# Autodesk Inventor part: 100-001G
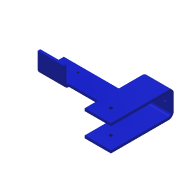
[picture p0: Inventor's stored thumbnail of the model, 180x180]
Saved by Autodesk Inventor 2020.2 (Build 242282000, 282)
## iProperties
Created: 2014-01
Part Number: 100-001G
Material: Ogólny
Document SubType Name: Modeling
Designer: F.Stasiak
Density: 1 g/cm^3
Appearance: Niebieska - farba ścienna - lśniąca
Manager: www.cadconsulting.pl
Company: Fabian Stasiak CAD Consulting
Author: F.Stasiak
Subject: Zbiór ćwiczeń. Autodesk Inventor 2020. Kurs podstawowy
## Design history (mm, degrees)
sketch "Szkic2"
  geometry: L1 (20, 120)-(20, 5); L2 (20, 5)-(-20, 5); L3 (-20, 5)-(-20, 120); L4 (-25, 120)-(-25, 0); L5 (-25, 0)-(25, 0); L6 (25, 0)-(25, 120); L7 (25, 120)-(20, 120); L8 (-20, 120)-(-25, 120); 2 further points
  constraints: 16 end point, 3 equal length, 3 perpendicular, 1 coincident, 1 midpoint, 1 parallel, 1 vertical, 2 other
  dimensions: "d2" = 5 distance of L6.end L1.start; "d3" = 120 distance of L5.end L6.end; "d4" = 50 distance between parallel lines of L6 L4
extrude "Wyciągnięcie proste1" new body sketch "Szkic2" stored distance "d5" = 50; taper "d6" = 0 deg
fillet "Zaokrąglenie1" dims "d7" = 5
fillet "Zaokrąglenie2" dims "d8" = 10
sketch "Szkic3"
  geometry: L1 (50, 0)-(50, -30) reference; L2 (12.5, -15)-(37.5, -15); 4 further points
  constraints: 3 coincident, 2 end point, 1 midpoint, 1 perpendicular
  dimensions: "d9" = 25 distance of L2.start L2.end
hole "Otwór1" sketch "Szkic3" at (12.5, -15), (37.5, -15) diameter "d10" = 6.5; stored, may be unused: countersink angle "d14" = 90 deg, drill point angle "d16" = 118 deg; dims "d11" = 6, "d12" = 4, "d13" = 2, "d15" = 8
sketch "Szkic4"
  geometry: L1 (0, 0)-(50, 0) reference; 3 further points
  constraints: 1 midpoint, 1 vertical alignment
  dimensions: "d17" = 25 distance from line of L1 point (25, 25)
hole "Otwór2" sketch "Szkic4" at (25, 25) diameter "d18" = 6.5; stored, may be unused: countersink angle "d22" = 90 deg, drill point angle "d24" = 118 deg; dims "d19" = 6, "d20" = 4, "d21" = 2, "d23" = 8
sketch "Szkic5"
  geometry: L1 (10, -25)-(120, -25) reference; L2 (120, -20)-(10, -20) reference; L3 (120, 25)-(10, 25) reference; L4 (10, -25)-(10, -20); L5 (50, -25)-(50, -20); 1 further point
  constraints: 4 end point, 2 perpendicular, 2 point on line
  dimensions: "d25" = 40 distance between parallel lines of L5 L4
extrude "Wyciągnięcie proste2" join sketch "Szkic5" distance "d26" = 150; taper "d27" = 0 deg
sketch "Szkic6"
  geometry: L1 (0, 5)-(-150, 5) reference; L2 (-150, 0)-(-150, 5) reference; L3 (0, 0)-(-150, 0) reference; L4 (-100, 0)-(-100, 5); 1 further point
  constraints: 2 end point, 2 point on line, 1 perpendicular
  dimensions: "d28" = 50 distance between parallel lines of L4 L2
extrude "Wyciągnięcie proste3" join sketch "Szkic6" distance "d29" = 10; taper "d30" = 0 deg
sketch "Szkic7"
  geometry: L1 (-150, 110)-(-150, 60) reference; L2 (-100, 60)-(-150, 60) reference; L3 (-100, 70)-(-100, 60) reference; L4 (-100, 65)-(-150, 65); 1 further point
  constraints: 2 end point, 1 midpoint, 1 perpendicular, 1 point on line
extrude "Wyciągnięcie proste4" join sketch "Szkic7" distance "d31" = 35; taper "d32" = 0 deg
fillet "Zaokrąglenie3" dims "d33" = 5
fillet "Zaokrąglenie4" dims "d34" = 10
sketch "Szkic8"
  geometry: C1 r 2.75 at (-140, 97.5) reference; C2 r 2.75 at (-110, 97.5) reference; 1 further point
hole "Otwór3" sketch "Szkic8" at (-140, 97.5), (-110, 97.5) diameter "d35" = 4.134; stored, may be unused: countersink angle "d39" = 90 deg, drill point angle "d41" = 118 deg; dims "d36" = 6, "d37" = 4, "d38" = 2, "d40" = 8
node "Bryła1"
node "Odniesienie1"
node "Odniesienie2"
